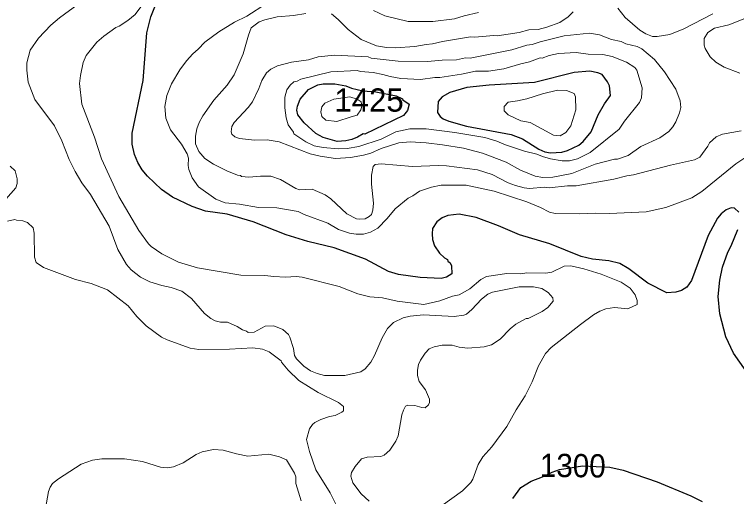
# Model space of a CAD drawing. Extents: x 598.3 to 623.2, y 6902.2 to 6930.1.
# Drawn here: x 604.89 to 607.371, y 6916.5 to 6918.158 of the extents above; entities that cross this region are included whole.
import ezdxf
from ezdxf.enums import TextEntityAlignment as Align

# ---------------------------------------------------------------- set-up
doc = ezdxf.new("R2010")
doc.units = 0
doc.header["$LTSCALE"] = 0.032
doc.layers.add('1', color=7, linetype='Continuous', lineweight=25)
doc.layers.add('2', color=7, linetype='Continuous', lineweight=13)
doc.layers.add('21', color=7, linetype='Continuous')
doc.layers.add('61', color=7, linetype='Continuous')

msp = doc.modelspace()

# ---------------------------------------------------------------- linework, layer by layer
at = {"layer": '1'}
for points in [[(607.3794, 6917.4777), (607.3641, 6917.4921), (607.3527, 6917.493), (607.3359, 6917.4865), (607.3187, 6917.4728), (607.3054, 6917.4576), (607.2742, 6917.3983), (607.2167, 6917.243), (607.2007, 6917.2198), (607.1823, 6917.2083), (607.1628, 6917.2025), (607.1312, 6917.201), (607.0668, 6917.2342), (607.0015, 6917.283), (606.9706, 6917.3012), (606.9329, 6917.3104), (606.8763, 6917.3165), (606.8374, 6917.3254), (606.7294, 6917.369), (606.6255, 6917.4005), (606.5531, 6917.431), (606.4768, 6917.4596), (606.4178, 6917.4712), (606.3789, 6917.4671), (606.3595, 6917.4582), (606.3416, 6917.4443), (606.3271, 6917.4215), (606.3256, 6917.4039), (606.3271, 6917.3841), (606.3338, 6917.3625), (606.3503, 6917.3373), (606.3679, 6917.3213), (606.3786, 6917.315), (606.3792, 6917.3099), (606.387, 6917.3036), (606.3919, 6917.2931), (606.3926, 6917.2664), (606.3747, 6917.2545), (606.3566, 6917.2503), (606.2837, 6917.2534), (606.2103, 6917.264), (606.1749, 6917.2746), (606.096, 6917.3163), (605.9885, 6917.3558), (605.8981, 6917.3773), (605.8233, 6917.4), (605.7106, 6917.4452), (605.621, 6917.4713), (605.5471, 6917.4817), (605.5011, 6917.4979), (605.4336, 6917.5298), (605.3952, 6917.5555), (605.3476, 6917.6023), (605.3294, 6917.624), (605.3138, 6917.6489), (605.3024, 6917.6765), (605.2951, 6917.7121), (605.295, 6917.7493), (605.3323, 6917.9313), (605.3453, 6918.0948), (605.359, 6918.1495), (605.3746, 6918.1904)], [(607.4048, 6916.9318), (607.3609, 6916.9933), (607.3344, 6917.0496), (607.3138, 6917.1287), (607.3083, 6917.1886), (607.3139, 6917.2445), (607.3229, 6917.2894), (607.3417, 6917.3404), (607.3533, 6917.3624), (607.3757, 6917.4181)], [(606.6028, 6916.4939), (606.6304, 6916.5309), (606.6658, 6916.5526), (606.7047, 6916.568), (606.7378, 6916.5842), (606.7635, 6916.5937), (606.8414, 6916.6064), (606.9354, 6916.6018), (606.9821, 6916.5912), (607.0981, 6916.5507), (607.2146, 6916.5029), (607.253, 6916.4838)]]:
    msp.add_lwpolyline(points, dxfattribs=at)
for points in [[(606.9349, 6917.9126), (606.9279, 6917.9259), (606.9091, 6917.9511), (606.8951, 6917.9577), (606.8672, 6917.9634), (606.8128, 6917.9585), (606.6765, 6917.9245), (606.5207, 6917.9148), (606.4451, 6917.9069), (606.3861, 6917.89), (606.3596, 6917.8743), (606.3458, 6917.8581), (606.3442, 6917.821), (606.3527, 6917.8067), (606.363, 6917.7989), (606.3829, 6917.7907), (606.4429, 6917.7742), (606.5973, 6917.7452), (606.6354, 6917.7299), (606.6924, 6917.6942), (606.7127, 6917.6857), (606.7316, 6917.6817), (606.7704, 6917.6849), (606.7909, 6917.69), (606.8296, 6917.708), (606.8445, 6917.7216), (606.8714, 6917.7539), (606.8962, 6917.8128), (606.9181, 6917.8504), (606.9381, 6917.8787)], [(606.1315, 6917.8913), (606.2012, 6917.8782), (606.2236, 6917.8683), (606.2252, 6917.864), (606.2468, 6917.8499), (606.2408, 6917.8272), (606.2268, 6917.8106), (606.0937, 6917.7465), (606.0888, 6917.7478), (606.0691, 6917.7364), (606.049, 6917.7283), (606.0284, 6917.7233), (605.9991, 6917.7206), (605.9508, 6917.7354), (605.9262, 6917.749), (605.8856, 6917.7848), (605.8641, 6917.8123), (605.8609, 6917.8287), (605.8625, 6917.8424), (605.8716, 6917.8665), (605.9006, 6917.9002), (605.9324, 6917.9165), (605.9512, 6917.9196), (605.9907, 6917.9196), (606.0289, 6917.9124), (606.0487, 6917.905), (606.0872, 6917.8954)]]:
    msp.add_lwpolyline(points, close=True, dxfattribs=at)
at = {"layer": '2'}
for points in [[(606.6248, 6917.221), (606.533, 6917.2033), (606.5164, 6917.1966), (606.4953, 6917.1788), (606.462, 6917.1429), (606.4432, 6917.1279), (606.4345, 6917.1241), (606.4006, 6917.119), (606.2951, 6917.1256), (606.2494, 6917.1207), (606.2254, 6917.1143), (606.1926, 6917.0987), (606.1724, 6917.0776), (606.1536, 6917.0463), (606.127, 6916.985), (606.1142, 6916.9625), (606.0947, 6916.9392), (606.0807, 6916.9296), (606.025, 6916.9168), (605.9559, 6916.9168), (605.9308, 6916.9236), (605.9073, 6916.9331), (605.8842, 6916.9482), (605.8588, 6916.9737), (605.8519, 6916.9856), (605.8486, 6917.0088), (605.8366, 6917.0486), (605.8313, 6917.0572), (605.8123, 6917.075), (605.7813, 6917.0867), (605.7519, 6917.0858), (605.7136, 6917.0657), (605.6936, 6917.0641), (605.6874, 6917.0689), (605.6736, 6917.0735), (605.6556, 6917.0853), (605.6222, 6917.0993), (605.5979, 6917.1003), (605.5801, 6917.1046), (605.5654, 6917.112), (605.5432, 6917.1292), (605.4986, 6917.1811), (605.4655, 6917.2061), (605.4289, 6917.2194), (605.3971, 6917.2257), (605.3549, 6917.2384), (605.3237, 6917.2541), (605.2916, 6917.2795), (605.275, 6917.2987), (605.2459, 6917.3493), (605.2161, 6917.4299), (605.1516, 6917.5394), (605.1215, 6917.5794), (605.0988, 6917.6176), (605.0779, 6917.6595), (605.0526, 6917.7229), (605.0274, 6917.775), (604.9601, 6917.866), (604.9376, 6917.9247), (604.9325, 6917.9661), (604.9325, 6917.9915), (604.944, 6918.0352), (604.9724, 6918.0763), (605.0151, 6918.1206), (605.0444, 6918.1467), (605.1093, 6918.1937)], [(605.3346, 6918.1979), (605.3047, 6918.1576), (605.2799, 6918.1368), (605.2503, 6918.1178), (605.2382, 6918.1125), (605.1974, 6918.0833), (605.1734, 6918.0627), (605.1362, 6918.0166), (605.1263, 6917.9931), (605.1167, 6917.9479), (605.1138, 6917.9206), (605.122, 6917.849), (605.1648, 6917.7365), (605.1893, 6917.6616), (605.2488, 6917.5314), (605.3174, 6917.4151), (605.3511, 6917.369), (605.3598, 6917.3603), (605.3968, 6917.3349)], [(605.7562, 6918.1955), (605.6891, 6918.1526), (605.646, 6918.1312), (605.5927, 6918.0984), (605.5438, 6918.0623), (605.5211, 6918.038), (605.5026, 6918.0227), (605.4811, 6917.9986), (605.4584, 6917.968), (605.4293, 6917.9194), (605.4133, 6917.8795), (605.4068, 6917.841), (605.4108, 6917.8014), (605.4269, 6917.7613), (605.4638, 6917.712), (605.4832, 6917.6792), (605.4877, 6917.6641), (605.4869, 6917.6387), (605.4891, 6917.6243), (605.5011, 6917.5964), (605.5222, 6917.5656), (605.5821, 6917.5226), (605.6147, 6917.5105), (605.6632, 6917.5061), (605.7292, 6917.4947), (605.7916, 6917.493), (605.8655, 6917.4802), (605.8858, 6917.4701), (605.9669, 6917.44), (606.0036, 6917.4184), (606.0415, 6917.4054), (606.0644, 6917.4024), (606.0894, 6917.4024), (606.1135, 6917.4089), (606.1383, 6917.4233), (606.1708, 6917.4564), (606.1984, 6917.4898), (606.2429, 6917.5262), (606.2594, 6917.5345), (606.2816, 6917.5504), (606.323, 6917.5641), (606.3564, 6917.5707), (606.4424, 6917.5707), (606.539, 6917.5498), (606.6507, 6917.5134), (606.6977, 6917.4939), (606.7289, 6917.4778), (606.7476, 6917.4737), (606.8331, 6917.4721), (606.8855, 6917.4752), (606.9351, 6917.4737), (607.0602, 6917.4797), (607.1288, 6917.4947), (607.2174, 6917.5277)], [(607.2899, 6918.1606), (607.1903, 6918.1084), (607.1418, 6918.0889), (607.0981, 6918.0816), (607.0825, 6918.0816), (607.0592, 6918.091), (607.0387, 6918.1034), (606.9884, 6918.1472), (606.9639, 6918.1792)], [(607.2271, 6917.658), (607.1442, 6917.6402), (607.0171, 6917.6064), (606.9939, 6917.6031), (606.9494, 6917.5919), (606.8207, 6917.5691), (606.7902, 6917.5683), (606.7276, 6917.5619), (606.7109, 6917.5635), (606.6597, 6917.5595), (606.6412, 6917.5618), (606.6115, 6917.5696), (606.5868, 6917.5793), (606.5317, 6917.6078), (606.4815, 6917.6235), (606.3744, 6917.6379), (606.3472, 6917.6388), (606.2581, 6917.6347), (606.1501, 6917.6444), (606.1295, 6917.6423), (606.1232, 6917.6353), (606.1174, 6917.6056), (606.1175, 6917.5739), (606.1239, 6917.5095), (606.1215, 6917.4855), (606.1167, 6917.4706), (606.1093, 6917.4631), (606.0957, 6917.4554), (606.0772, 6917.4535), (606.0656, 6917.4555), (606.0325, 6917.4722), (605.9772, 6917.524), (605.9578, 6917.5377), (605.9127, 6917.557), (605.8699, 6917.5554), (605.8566, 6917.5593), (605.804, 6917.5903), (605.7708, 6917.6022), (605.736, 6917.6023), (605.6951, 6917.5984), (605.6701, 6917.6008), (605.6672, 6917.6039), (605.6568, 6917.6052), (605.6199, 6917.62), (605.5738, 6917.643), (605.5443, 6917.6632), (605.5235, 6917.6871), (605.512, 6917.7125), (605.512, 6917.7389), (605.5169, 6917.7645), (605.5248, 6917.7867), (605.5376, 6917.809), (605.575, 6917.8628), (605.6214, 6917.9151), (605.6449, 6917.9507), (605.6759, 6918.0226), (605.6946, 6918.087), (605.7039, 6918.1114), (605.7312, 6918.1324), (605.7502, 6918.1394), (605.7927, 6918.1495), (605.8493, 6918.1544), (605.8911, 6918.1617)], [(605.9792, 6918.16), (606.0022, 6918.141), (606.0373, 6918.1066), (606.0816, 6918.0715), (606.1345, 6918.0499), (606.1685, 6918.0443), (606.1986, 6918.0428), (606.2657, 6918.0477), (606.3043, 6918.0548), (606.3268, 6918.0564), (606.3606, 6918.0644), (606.4567, 6918.0807), (606.4717, 6918.0801), (606.5358, 6918.0856), (606.549, 6918.0841), (606.6244, 6918.0955), (606.6574, 6918.105), (606.6897, 6918.1067), (606.7192, 6918.114), (606.7641, 6918.1308), (606.7931, 6918.1499), (606.8103, 6918.1666)], [(606.4845, 6918.165), (606.4359, 6918.1536), (606.4022, 6918.1424), (606.3281, 6918.1342), (606.243, 6918.1334), (606.1623, 6918.1532), (606.1236, 6918.1712)], [(607.4, 6918.1437), (607.3453, 6918.1228), (607.2953, 6918.1107), (607.2725, 6918.0959), (607.2605, 6918.0751), (607.2604, 6918.0528), (607.2639, 6918.0411), (607.281, 6918.0117), (607.3004, 6917.9937), (607.3285, 6917.9766), (607.3821, 6917.9562)], [(607.3869, 6917.7574), (607.3234, 6917.7462), (607.3016, 6917.7366), (607.2779, 6917.7167), (607.2728, 6917.7048), (607.2456, 6917.6668), (607.2271, 6917.658)], [(607.2174, 6917.5277), (607.2523, 6917.5489), (607.369, 6917.6438), (607.4029, 6917.6672)], [(604.8756, 6917.6363), (604.893, 6917.6207), (604.9, 6917.5929), (604.9, 6917.5765), (604.8951, 6917.5618), (604.8602, 6917.5228)], [(604.8668, 6917.447), (604.8909, 6917.4533), (604.8971, 6917.4502), (604.9192, 6917.4483), (604.9347, 6917.4428), (604.9539, 6917.4237), (604.9575, 6917.4064), (604.9587, 6917.3233), (604.9643, 6917.3049), (604.9899, 6917.2882), (605.0997, 6917.247), (605.154, 6917.233), (605.2098, 6917.2107), (605.2811, 6917.1556), (605.3104, 6917.1199), (605.3428, 6917.0875), (605.3949, 6917.0485), (605.415, 6917.0392), (605.4944, 6917.0108), (605.5236, 6917.0058), (605.6294, 6917.0065), (605.7093, 6917.0114), (605.7425, 6917.0066), (605.7656, 6916.9975), (605.8071, 6916.9672), (605.8083, 6916.9622), (605.8309, 6916.9345), (605.8676, 6916.8992), (605.934, 6916.8583), (606.0035, 6916.8232), (606.021, 6916.8096), (606.0205, 6916.7951), (606.0154, 6916.7899), (605.9923, 6916.7791), (605.9729, 6916.7759), (605.9428, 6916.7651), (605.9218, 6916.7545), (605.9141, 6916.7479), (605.9037, 6916.7327), (605.8941, 6916.6962), (605.9034, 6916.6546), (605.9255, 6916.5924), (605.9749, 6916.513), (605.9944, 6916.4739)], [(605.3968, 6917.3349), (605.454, 6917.3063), (605.5186, 6917.2872), (605.6682, 6917.2616), (605.7502, 6917.2608), (605.781, 6917.2567), (605.8219, 6917.2551), (605.8576, 6917.2566), (605.879, 6917.2542), (606.0064, 6917.2227), (606.0697, 6917.1968), (606.1116, 6917.1871), (606.1553, 6917.1839), (606.2055, 6917.1725), (606.2967, 6917.1611), (606.3523, 6917.1731), (606.3957, 6917.1888), (606.4183, 6917.1944), (606.4545, 6917.215), (606.4922, 6917.2461), (606.5118, 6917.2566), (606.5824, 6917.2672), (606.6289, 6917.2664), (606.6507, 6917.2696), (606.716, 6917.2681), (606.7369, 6917.2713), (606.7789, 6917.2923), (606.8021, 6917.2939), (606.8466, 6917.2834), (606.9058, 6917.2651), (606.975, 6917.2371), (607.006, 6917.2166), (607.0233, 6917.1943), (607.0297, 6917.1747), (607.0297, 6917.1608), (606.9975, 6917.1458), (606.9524, 6917.1506), (606.9219, 6917.1459), (606.9017, 6917.1376), (606.8798, 6917.1249), (606.8346, 6917.0924), (606.7344, 6917.013), (606.7144, 6916.9924), (606.6907, 6916.9502), (606.6686, 6916.8946), (606.6451, 6916.8463), (606.6142, 6916.7988), (606.5823, 6916.7416), (606.5302, 6916.6712), (606.4994, 6916.6364), (606.484, 6916.6109), (606.4654, 6916.5596), (606.4584, 6916.5487), (606.4293, 6916.5202), (606.3566, 6916.4676)], [(606.1086, 6916.4842), (606.0815, 6916.5091), (606.0525, 6916.5472), (606.0463, 6916.5708), (606.0481, 6916.5826), (606.0612, 6916.6039), (606.0827, 6916.6301), (606.1019, 6916.636), (606.1493, 6916.6383), (606.1602, 6916.6426), (606.1802, 6916.6597), (606.2009, 6916.6912), (606.2081, 6916.7086), (606.2211, 6916.7815), (606.2265, 6916.7972), (606.2342, 6916.8106), (606.2416, 6916.8147), (606.2662, 6916.8129), (606.2894, 6916.8059), (606.3008, 6916.8058), (606.3126, 6916.8157), (606.3165, 6916.8242), (606.3166, 6916.8346), (606.3029, 6916.8671), (606.2802, 6916.8957), (606.2746, 6916.917), (606.2745, 6916.9347), (606.2789, 6916.9545), (606.2849, 6916.9691), (606.3012, 6916.9936), (606.3153, 6917.0078), (606.3323, 6917.0155), (606.3593, 6917.0203), (606.3938, 6917.0203), (606.4181, 6917.0138), (606.4482, 6917.0107), (606.5042, 6917.0155), (606.5293, 6917.0219), (606.5596, 6917.0415), (606.5932, 6917.0768), (606.6124, 6917.0933), (606.6481, 6917.1125), (606.6558, 6917.1126), (606.7032, 6917.1371), (606.7232, 6917.15), (606.7408, 6917.1721), (606.74, 6917.1836), (606.724, 6917.2015), (606.7027, 6917.2154), (606.6739, 6917.221), (606.6248, 6917.221)], [(605.8754, 6916.4852), (605.857, 6916.5446), (605.8568, 6916.5683), (605.8522, 6916.581), (605.8251, 6916.626), (605.8008, 6916.6367), (605.7644, 6916.6456), (605.6923, 6916.6391), (605.6526, 6916.647), (605.607, 6916.6601), (605.5741, 6916.6625), (605.535, 6916.6542), (605.5142, 6916.6446), (605.4697, 6916.6158), (605.437, 6916.6027), (605.4151, 6916.5985), (605.3921, 6916.6011), (605.3301, 6916.6204), (605.2681, 6916.6302), (605.1904, 6916.6301), (605.1585, 6916.6253), (605.1193, 6916.6114), (605.041, 6916.5612), (605.0211, 6916.5447), (605.0128, 6916.5327), (605.0069, 6916.5179), (604.9939, 6916.4399)]]:
    msp.add_lwpolyline(points, dxfattribs=at)
for points in [[(605.7401, 6917.9311), (605.7558, 6917.9571), (605.7707, 6917.9701), (605.794, 6917.9817), (605.8417, 6917.9934), (605.9004, 6918.002), (605.9335, 6918.0119), (605.9902, 6918.0184), (606.1053, 6918.0119), (606.1153, 6918.0078), (606.2084, 6917.9974), (606.3099, 6917.9958), (606.3593, 6918.0006), (606.4087, 6918.0023), (606.4403, 6918.0087), (606.4565, 6918.0071), (606.5989, 6918.0366), (606.6509, 6918.0524), (606.6689, 6918.0544), (606.6966, 6918.0638), (606.7791, 6918.0849), (606.8665, 6918.0936), (606.9007, 6918.088), (606.9421, 6918.0719), (606.9745, 6918.0654), (606.9909, 6918.0573), (607.0296, 6918.0476), (607.0462, 6918.0401), (607.0888, 6918.0029), (607.1235, 6917.9607), (607.1624, 6917.9005), (607.178, 6917.8612), (607.1796, 6917.8377), (607.1755, 6917.8202), (607.1628, 6917.789), (607.1522, 6917.7715), (607.1385, 6917.7556), (607.1072, 6917.7333), (607.0424, 6917.704), (606.9988, 6917.6734), (606.9624, 6917.66), (606.9521, 6917.6598), (606.8857, 6917.6436), (606.805, 6917.6113), (606.7404, 6917.5983), (606.7051, 6917.5975), (606.679, 6917.6017), (606.6294, 6917.622), (606.5792, 6917.6495), (606.4985, 6917.6809), (606.433, 6917.6977), (606.3609, 6917.71), (606.3043, 6917.7165), (606.2494, 6917.7197), (606.211, 6917.7166), (606.15, 6917.6974), (606.1143, 6917.6804), (606.0894, 6917.6736), (606.0451, 6917.6658), (605.9931, 6917.6631), (605.9407, 6917.6708), (605.9066, 6917.6789), (605.7996, 6917.7197), (605.7587, 6917.7271), (605.7144, 6917.7262), (605.6629, 6917.7312), (605.6478, 6917.7373), (605.6367, 6917.7467), (605.6343, 6917.7548), (605.6367, 6917.7725), (605.6448, 6917.786), (605.6929, 6917.8375), (605.7077, 6917.8579), (605.7295, 6917.9029)], [(605.8195, 6917.873), (605.8262, 6917.8988), (605.8374, 6917.9148), (605.8503, 6917.9259), (605.861, 6917.9282), (605.8741, 6917.9351), (605.9777, 6917.9602), (606.0678, 6917.9649), (606.0789, 6917.9618), (606.1229, 6917.9586), (606.1558, 6917.952), (606.1809, 6917.9441), (606.2182, 6917.9375), (606.2855, 6917.9343), (606.3347, 6917.9407), (606.352, 6917.9408), (606.4265, 6917.9529), (606.4748, 6917.9634), (606.5188, 6917.9634), (606.5714, 6917.9706), (606.6302, 6917.9885), (606.6593, 6917.995), (606.6964, 6918.0086), (606.7029, 6918.008), (606.7273, 6918.0169), (606.7592, 6918.0232), (606.82, 6918.0266), (606.8609, 6918.0217), (606.9119, 6918.02), (606.9438, 6918.0136), (606.9928, 6917.994), (607.0215, 6917.9757), (607.0289, 6917.9666), (607.0468, 6917.9056), (607.0452, 6917.8714), (607.0381, 6917.8554), (606.9862, 6917.7911), (606.9678, 6917.7638), (606.8687, 6917.6827), (606.8252, 6917.6618), (606.7972, 6917.655), (606.7719, 6917.655), (606.7319, 6917.6614), (606.7046, 6917.6692), (606.6852, 6917.6775), (606.6426, 6917.6874), (606.5772, 6917.7095), (606.548, 6917.7217), (606.5066, 6917.7343), (606.4035, 6917.752), (606.3048, 6917.765), (606.2492, 6917.765), (606.2007, 6917.7545), (606.1505, 6917.7293), (606.0733, 6917.7044), (606.0331, 6917.6971), (606.0024, 6917.6963), (605.951, 6917.7003), (605.92, 6917.7065), (605.8917, 6917.7198), (605.8506, 6917.7472), (605.8487, 6917.753), (605.8303, 6917.7786), (605.8237, 6917.8029), (605.8195, 6917.8363)], [(606.5731, 6917.827), (606.5725, 6917.8409), (606.587, 6917.8565), (606.619, 6917.8606), (606.6507, 6917.8678), (606.7047, 6917.8849), (606.7557, 6917.8977), (606.7872, 6917.8961), (606.8136, 6917.8862), (606.8175, 6917.875), (606.8185, 6917.8301), (606.802, 6917.7751), (606.7849, 6917.7516), (606.7648, 6917.7401), (606.7428, 6917.7423), (606.6619, 6917.7862), (606.6297, 6917.7926), (606.5868, 6917.8123)], [(606.0425, 6917.8743), (606.0681, 6917.867), (606.0809, 6917.8574), (606.0835, 6917.8421), (606.0804, 6917.8295), (606.0673, 6917.8121), (606.0468, 6917.8056), (605.9984, 6917.7894), (605.9599, 6917.7949), (605.9464, 6917.8071), (605.9427, 6917.8235), (605.9466, 6917.8401), (605.9571, 6917.8533), (605.9871, 6917.867)]]:
    msp.add_lwpolyline(points, close=True, dxfattribs=at)

# ---------------------------------------------------------------- texts
at = {"layer": '21'}
msp.add_text('1425', height=0.08, dxfattribs=at).set_placement((605.9896, 6917.8237))
at = {"layer": '61', "width": 0.95}
msp.add_text('1300', height=0.08, rotation=359.341, dxfattribs=at).set_placement((606.8082, 6916.5668), align=Align.CENTER)

doc.saveas('drawing.dxf')
